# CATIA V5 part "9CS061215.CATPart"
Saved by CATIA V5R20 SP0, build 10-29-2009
Part number: 9CS061215
Revision: ANY
Definition: UNKNOWN
Nomenclature: 9CS061215
Source: Unknown
Bounding box of the stored display mesh (mm): x -5.85 to 5.85, y 0 to 15, z -6 to 6
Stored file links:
  C:\Users\Utente\Desktop\IO LAVORO\3D X SITO CF\CUMSA\3D files PW\pw060630\pw060630_ejection\9CS061215.CATPart
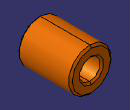
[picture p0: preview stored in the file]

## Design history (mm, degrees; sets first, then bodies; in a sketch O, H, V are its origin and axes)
Body1 "Revolución1" (main body)
  Solid1: solid without history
